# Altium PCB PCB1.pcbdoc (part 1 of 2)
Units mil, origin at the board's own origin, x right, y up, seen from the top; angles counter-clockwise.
Board outline 3543.31 x 2362.2 mil, 2 copper layers (Top Layer, Bottom Layer), stack 62.206 mil thick; 105 components, 91 nets, 439 pads, 301 vias.
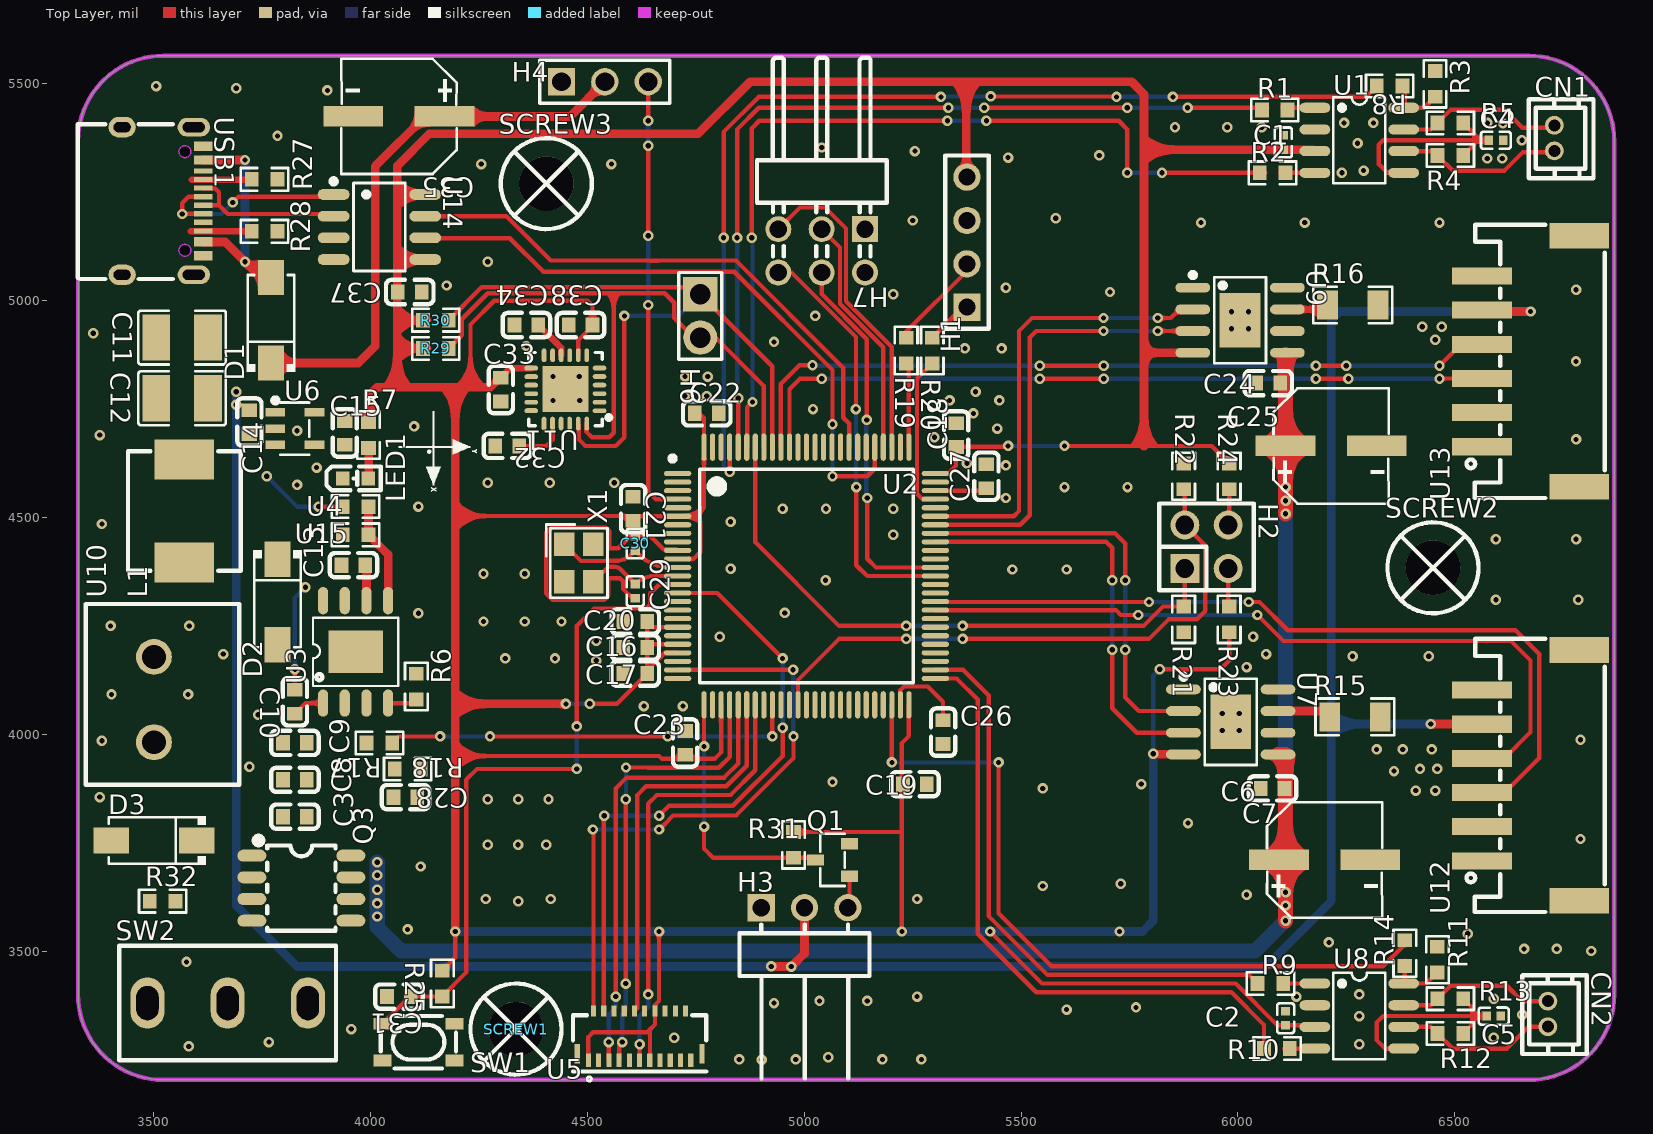
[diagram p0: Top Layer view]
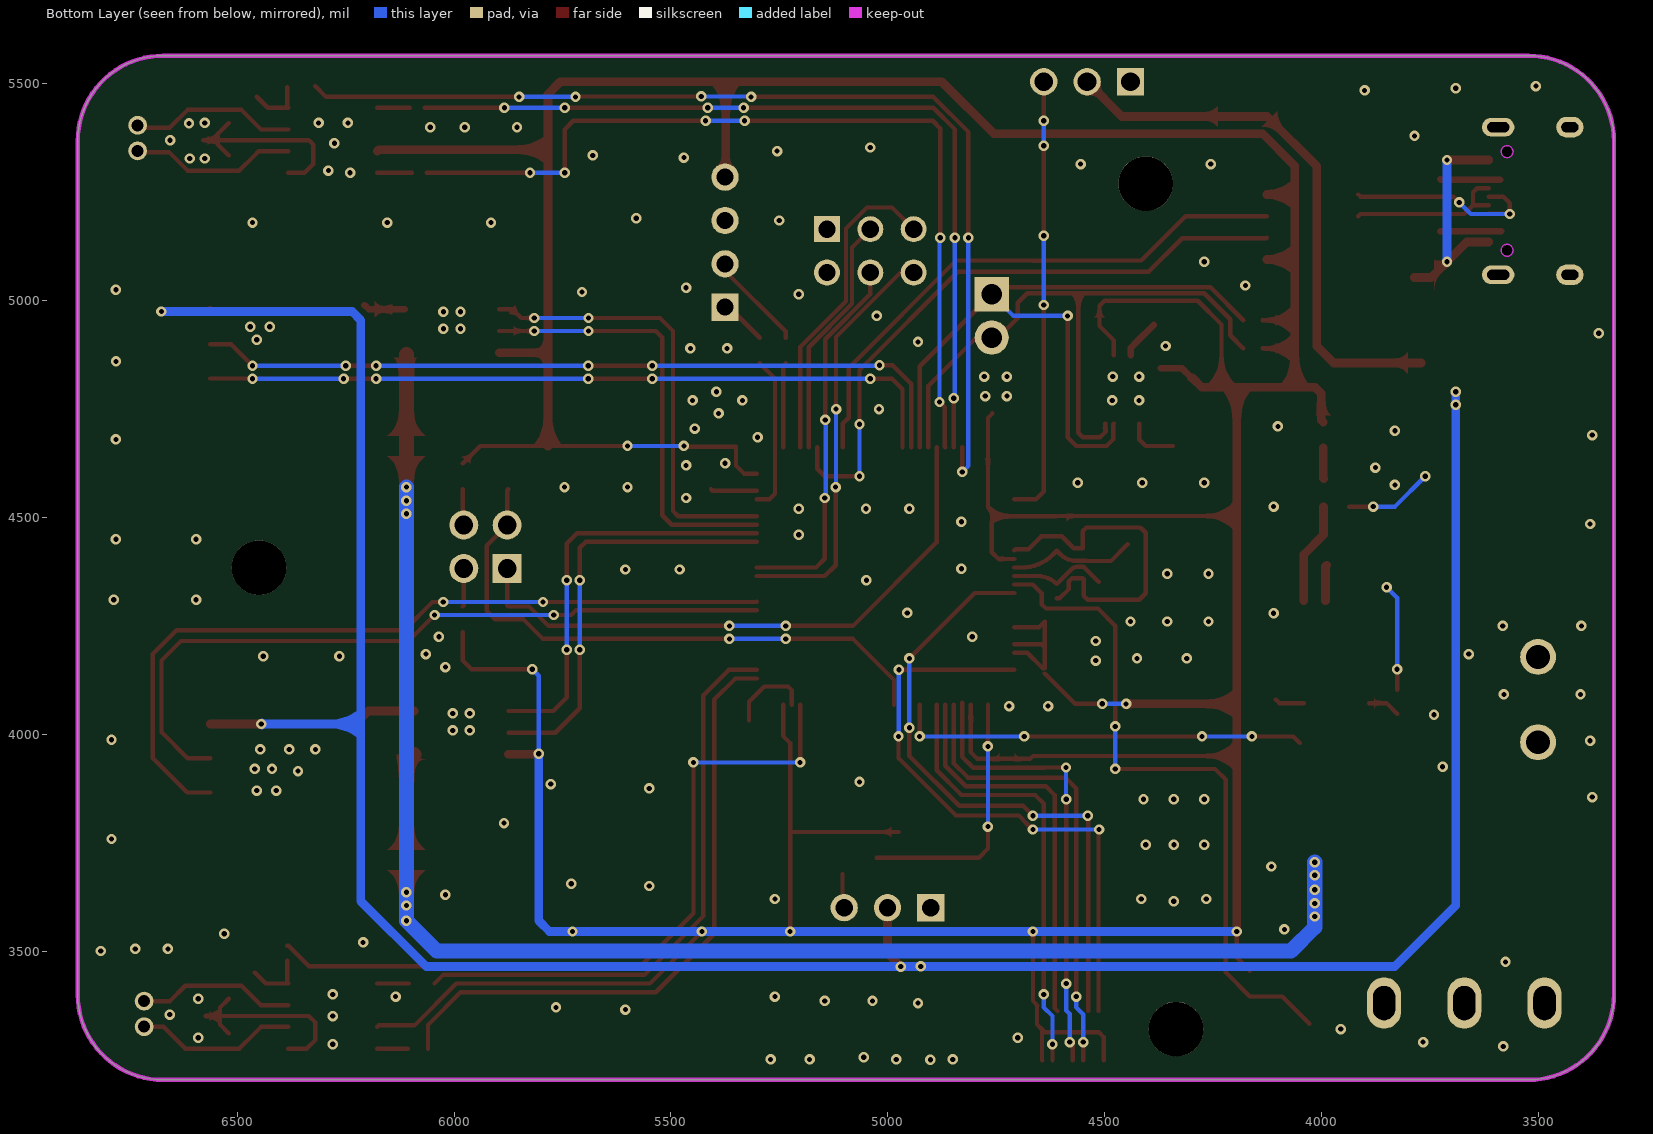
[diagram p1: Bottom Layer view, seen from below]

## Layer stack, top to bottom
Top Solder Mask Layer: solder mask 0.394, Dk 3.3
Top Layer: signal copper 1.379
Dielectric1: surface 59.449, FR4, Dk 4.5
Bottom Layer: signal copper 1.378
Bottom Solder Mask Layer: solder mask 0.394, Dk 3.3

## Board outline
3521.65,5565 ccw(c3521.65,5368.15) 3324.8,5368.15 3324.8,3399.65 ccw(c3521.65,3399.65) 3521.65,3202.8 6671.26,3202.8 ccw(c6671.26,3399.65) 6868.11,3399.65 6868.11,5368.15 ccw(c6671.26,5368.15) 6671.26,5565

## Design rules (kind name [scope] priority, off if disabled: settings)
BoardOutlineClearance copperThickness2oz_1 [All] p2 off: genericclearance=7.99 ignorepadtopadclearanceinfootprint=FALSE except(0: Arc-SplitContinuation Track-SplitContinuation SMDPad-SplitContinuation THPad-SplitContinuation Via-SplitContinuation Fill-SplitContinuation Region-SplitContinuation Poly-SplitContinuation Text-SplitContinuation Hole-SplitContinuation; 5.98: Arc-CutoutEdge SMDPad-CutoutEdge THPad-CutoutEdge Via-CutoutEdge Fill-CutoutEdge Region-CutoutEdge Text-CutoutEdge; 6.93: Hole-OutlineEdge Hole-CutoutEdge; 10: Poly-OutlineEdge Poly-CutoutEdge; 11.81: Arc-OutlineEdge Track-OutlineEdge SMDPad-OutlineEdge THPad-OutlineEdge Via-OutlineEdge Fill-OutlineEdge Region-OutlineEdge Text-OutlineEdge Track-CutoutEdge)
BoardOutlineClearance copperThickness1oz_1 [All] p4: genericclearance=4.02 ignorepadtopadclearanceinfootprint=FALSE except(0: Arc-SplitContinuation Track-SplitContinuation SMDPad-SplitContinuation THPad-SplitContinuation Via-SplitContinuation Fill-SplitContinuation Region-SplitContinuation Poly-SplitContinuation Text-SplitContinuation Hole-SplitContinuation; 6: SMDPad-CutoutEdge THPad-CutoutEdge Via-CutoutEdge Fill-CutoutEdge Region-CutoutEdge Text-CutoutEdge; 6.93: Hole-OutlineEdge Hole-CutoutEdge; 10: Poly-OutlineEdge Poly-CutoutEdge; 11.8: Arc-OutlineEdge Track-OutlineEdge SMDPad-OutlineEdge THPad-OutlineEdge Via-OutlineEdge Fill-OutlineEdge Region-OutlineEdge Text-OutlineEdge; 11.81: Arc-CutoutEdge Track-CutoutEdge)
Clearance copperThickness2oz [All] p1 off: gap=7.99 ignorepadtopadclearanceinfootprint=FALSE except(5.98: SMDPad-Track SMDPad-SMDPad THPad-Track SMDPad-THPad THPad-THPad Track-Via SMDPad-Via THPad-Via Via-Via Fill-Track Region-Track Fill-SMDPad Region-SMDPad Fill-THPad Region-THPad Fill-Via Region-Via Fill-Fill Fill-Region Region-Region Arc-Track Arc-SMDPad Arc-THPad Arc-Via Fill-Arc Region-Arc Arc-Arc Text-Track SMDPad-Text Text-THPad Text-Via Fill-Text Region-Text Arc-Text Text-Text; 6.93: Hole-Track Hole-SMDPad Hole-THPad Hole-Via Fill-Hole Region-Hole Hole-Arc Hole-Text; 10: Poly-Track Poly-SMDPad Poly-THPad Poly-Via Poly-Fill Poly-Region Poly-Poly Poly-Arc Poly-Text Poly-Hole)
Clearance copperThickness1oz [All] p3: gap=4.02 ignorepadtopadclearanceinfootprint=FALSE except(5.98: SMDPad-Track SMDPad-SMDPad THPad-Track SMDPad-THPad THPad-THPad Track-Via SMDPad-Via THPad-Via Via-Via Fill-Track Region-Track Fill-SMDPad Region-SMDPad Fill-THPad Region-THPad Fill-Via Region-Via Fill-Fill Fill-Region Region-Region; 6: Arc-Track Arc-SMDPad Arc-THPad Arc-Via Fill-Arc Region-Arc Arc-Arc Text-Track SMDPad-Text Text-THPad Text-Via Fill-Text Region-Text Arc-Text Text-Text; 6.93: Hole-Track Hole-SMDPad Hole-THPad Hole-Via Fill-Hole Region-Hole Hole-Arc Hole-Text; 10: Poly-Track Poly-SMDPad Poly-THPad Poly-Via Poly-Fill Poly-Region Poly-Poly Poly-Arc Poly-Text Poly-Hole)
Creepage creepage [All] p1: checkdistance=0 ignoreinternallayers=TRUE applytopolygonpour=TRUE
DiffPairsRouting differentialPair [All] p1: maxlimit=6 minlimit=6 mostfreqgap=6 toplayer_minwidth=5 toplayer_prefwidth=10 toplayer_maxwidth=100 toplayer_mingap=6 toplayer_prefgap=6 toplayer_maxgap=6 bottomlayer_minwidth=5 bottomlayer_prefwidth=10 bottomlayer_maxwidth=100 bottomlayer_mingap=6 bottomlayer_prefgap=6 bottomlayer_maxgap=6 maxuncoupledlength=10
HoleToHoleClearance otherClearance [All] p1: gap=11.81 allowstackedmicrovias=TRUE
Length netLength [All] p1: minlimit=0 maxlimit=0
MatchedLengths netLengthTolerance [All] p1: tolerance=1000
PasteMaskExpansion pasteMaskExpansion [All] p1: expansion=0
PlaneConnect innerPlane [All] p1: planeconnectstyle=Relief reliefexpansion=20 reliefentries=4 reliefconductorwidth=10 reliefairgap=10
PolygonConnect "copperRegion_Top Layer" [(InNet('BAT') OR InNet('3V3') OR InNet('12V') OR InNet('$1N58') OR InNet('$1N321') OR InNet('$1N322') OR InNet('BAT_ADC') OR InNet('GND') OR InNet('MOTOR1_OUT1') OR InNet('MOTOR1_OUT2') OR InNet('MOTOR2_OUT1') OR InNet('MOTOR2_OUT2')) And OnLayer('Top Layer')] p1: connectstyle=Direct reliefconductorwidth=10 reliefentries=4 polygonreliefangle="90 Angle" airgapwidth=10 via.connectstyle=Relief via.reliefconductorwidth=10 via.reliefentries=4 via.polygonreliefangle="90 Angle" via.airgapwidth=10
PolygonConnect "copperRegion_Bottom Layer" [(InNet('BAT') OR InNet('3V3') OR InNet('12V') OR InNet('$1N58') OR InNet('$1N321') OR InNet('$1N322') OR InNet('BAT_ADC') OR InNet('GND') OR InNet('MOTOR1_OUT1') OR InNet('MOTOR1_OUT2') OR InNet('MOTOR2_OUT1') OR InNet('MOTOR2_OUT2')) And OnLayer('Bottom Layer')] p2: connectstyle=Direct reliefconductorwidth=10 reliefentries=4 polygonreliefangle="90 Angle" airgapwidth=10 via.connectstyle=Relief via.reliefconductorwidth=10 via.reliefentries=4 via.polygonreliefangle="90 Angle" via.airgapwidth=10
PolygonConnect copperRegion [(InNet('BAT') OR InNet('3V3') OR InNet('12V') OR InNet('$1N58') OR InNet('$1N321') OR InNet('$1N322') OR InNet('BAT_ADC') OR InNet('GND') OR InNet('MOTOR1_OUT1') OR InNet('MOTOR1_OUT2') OR InNet('MOTOR2_OUT1') OR InNet('MOTOR2_OUT2'))] p3: connectstyle=Direct reliefconductorwidth=10 reliefentries=4 polygonreliefangle="90 Angle" airgapwidth=10 via.connectstyle=Relief via.reliefconductorwidth=10 via.reliefentries=4 via.polygonreliefangle="90 Angle" via.airgapwidth=10
RoutingVias viaSize [All] p1: holewidth=12.01 width=24.02 viastyle="Through Hole" minholewidth=11.81 minwidth=19.68 maxholewidth=248.03 maxwidth=393.7
SolderMaskExpansion solderMaskExpansion [IsVia] p1: expansion=-1000 istentingtop=TRUE
SolderMaskExpansion solderMaskExpansion [All] p2: expansion=2 istentingtop=FALSE
Width copperThickness2oz_2 [All] p1 off: maxlimit=100 minlimit=8 preferedwidth=10
Width copperThickness1oz_2 [All] p2: maxlimit=100 minlimit=5 preferedwidth=10

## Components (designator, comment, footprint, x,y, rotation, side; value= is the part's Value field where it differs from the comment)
C1 "4.7uF" C0402 6105,5365 r270 top
C2 "4.7uF" C0402 6110,3345 r270 top
C3 "2.2uF" C0603 3825,3810 r180 top
C4 "100pF" C0402 6595,5370 r0 top
C5 "100pF" C0402 6590,3350 r0 top
C6 "100nF" C0603 6080,3875 r0 top
C7 "47uF" CAP-SMD_BD6.3-L6.6-W6.6-LS7.3-FD 6200,3710 r0 top
C8 "2.2uF" C0603 3825,3895 r180 top
C9 "100nF" C0603 3825,3980 r0 top
C10 "100nF" C0603 3825,4075 r270 top
C11 "47uF" C1210 3565,4915 r0 top
C12 "47uF" C1210 3565,4775 r0 top
C13 "22nF" C0603 3960,4390 r0 top
C14 "100nF" C0603 3720,4720 r90 top
C15 "100nF" C0603 3940,4695 r90 top
C16 "100nF" C0603 4610,4200 r180 top
C17 "100nF" C0603 4610,4140 r0 top
C18 "100nF" C0603 5350,4690 r270 top
C19 "100nF" C0603 5255,3885 r180 top
C20 "100nF" C0603 4610,4260 r0 top
C21 "100nF" C0603 4605,4520 r270 top
C22 "100nF" C0603 4775,4740 r180 top
C23 "100nF" C0603 4725,3980 r270 top
C24 "100nF" C0603 6070,4810 r0 top
C25 "47uF" CAP-SMD_BD6.3-L6.6-W6.6-LS7.3-FD 6215,4665 r0 top
C26 "2.2uF" C0603 5320,4005 r270 top
C27 "2.2uF" C0603 5420,4595 r90 top
C28 "100nF" C0603 4080,3855 r180 top
C29 "12pF" C0402 4610,4330 r90 top
C30 "12pF" C0402 4610,4440 r270 top
C31 "100nF" C0603 4065,3395 r0 top
C32 "2.2nF" C0603 4315,4665 r180 top
C33 "100nF" C0603 4300,4795 r270 top
C34 "100nF" C0603 4358.93,4943.93 r0 top
C35 "100uF" CAP-SMD_BD6.3-L6.6-W6.6-LS7.3-FD-H7.7 4065,5425 r180 top
C37 "100nF" C0603 4090,5020 r180 top
C38 "10nF" C0603 4483.93,4943.93 r0 top
CN1 "ZH1.5-2A" CONN-TH_ZH-1.5-2A 6730,5375 r270 top
CN2 "ZH1.5-2A" CONN-TH_ZH-1.5-2A 6715,3355 r270 top
D1 "SS54" SMA_L4.4-W2.8-LS5.4-R-RD 3770,4955 r90 top
D2 "SS54" SMA_L4.4-W2.8-LS5.4-R-RD 3785,4305 r270 top
D3 "SS54" SMA_L4.4-W2.8-LS5.4-R-RD 3500,3755 r180 top
H1 "LAIL-PZ2.54-4P-L" CONN-TH_LAIL-PZ2.54-4P-L 5375,5135 r90 top
H2 "PZ254V-12-4P" HDR-TH_4P-P2.54-V-M-R2-C2-S2.54 5927.67,4432.33 r0 top
H3 "LAIL-PZ2.54-3P-W" HDR-TH_LAIL-PZ2.54-3P-W 5000.39,3600 r0 top locked
H4 "LAIL-PZ2.54-3P-L" HDR-TH_3P-P2.54-V-M-1 4540,5505 r0 top
H6 "PZ254V-11-02P" HDR-TH_2P-P2.54-V-M 4760,4965 r270 top
H7 "HC-PZ254-13.8L-2x3PWA" HDR-TH_6P-P2.54-H-M-R2-C3-S2.54-W12.9 5040,5115 r180 top
L1 "4.7uH" IND-SMD_L7.0-W6.6_AAPS0630 3570,4515 r90 top
LED1 "KT-0603R" LED-SMD_L1.6-W0.8-R-RD 3965,4590 r0 top
Q1 "PMBT3904" SOT-23-3_L2.9-W1.3-P1.90-LS2.4-BR 5065,3710 r0 top
Q3 "NCE4435" SOP-8_L5.0-W4.0-P1.27-LS6.2-BL 3840,3645 r270 top
R1 "100Ω" R0603 6085,5440 r0 top
R2 "100Ω" R0603 6080,5295 r0 top
R3 "10kΩ" R0603 6455,5500 r90 top
R4 "60Ω" R0603 6490,5335 r180 top
R5 "60Ω" R0603 6490,5410 r180 top
R6 "49.9kΩ" R0603 4105,4110 r270 top
R7 "10kΩ" R0603 3995,4690 r270 top
R8 "100Ω" R0603 6350,5495 r180 top
R9 "100Ω" R0603 6075,3425 r0 top
R10 "100Ω" R0603 6090,3275 r0 top
R11 "10kΩ" R0603 6460,3480 r90 top
R12 "60Ω" R0603 6490,3310 r180 top
R13 "60Ω" R0603 6490,3390 r180 top
R14 "100Ω" R0603 6385,3495 r90 top
R15 "200mΩ" R1206 6270,4040 r0 top
R16 "200mΩ" R1206 6265,4990 r0 top
R17 "30kΩ" R0603 4020,3980 r180 top
R18 "7.5kΩ" R0603 4085,3920 r180 top
R19 "100Ω" R0603 5235,4885 r270 top
R20 "100Ω" R0603 5295,4885 r270 top
R21 "10kΩ" R0603 5875,4265 r90 top
R22 "10kΩ" R0603 5875,4595 r90 top
R23 "1kΩ" R0603 5980,4265 r90 top
R24 "1kΩ" R0603 5980,4595 r90 top
R25 "10kΩ" R0603 4165,3425 r90 top
R27 "5.1kΩ" R0603 3755,5280 r180 top
R28 "5.1kΩ" R0603 3755,5160 r180 top
R29 "4.7kΩ" R0603 4150,4890 r180 top
R30 "4.7kΩ" R0603 4150,4955 r180 top
R31 "4.7kΩ" R0603 4975,3745 r90 top
R32 "10kΩ" R0603 3520,3615 r0 top
SCREW1 "" M3螺丝 4335,3320 r0 top
SCREW2 "" M3螺丝 6450,4383.9 r0 top
SCREW3 "" M3螺丝 4405,5270 r0 top
SW1 "SKRPACE010" KEY-SMD_4P-L4.2-W3.2-P2.20-LS4.6 4110,3290 r0 top
SW2 "SS-12D10L5" SW-TH_SS-12D10L5 3670,3380 r0 top
U1 "SN65HVD230DR" SOIC-8_L4.9-W3.9-P1.27-LS6.0-BL 6280,5370 r270 top
U2 "STM32F407VET6" LQFP-100_L14.0-W14.0-P0.50-LS16.0-BL 5005,4365 r270 top locked
U3 "LMR14030SDDAR" SO-8_L4.9-W3.9-P1.27-LS6.0-BL-EP 3965,4190 r0 top
U4 "91kΩ" R0603 3965,4525 r180 top
U5 "FH26W-21S-0.3SHW(60)" FPC-SMD_21P-P0.30_HDGC_0.3K-QX-21PWB 4620,3305 r0 top locked
U6 "RT9013-33GB" SOT-23-5_L3.0-W1.7-P0.95-LS2.8-BL 3825,4705 r270 top
U7 "DRV8870DDAR" HSOP-8_L5.0-W4.0-P1.27-LS6.2-BL-EP 5983.51,4028.51 r270 top
U8 "SN65HVD230DR" SOIC-8_L4.9-W3.9-P1.27-LS6.0-BL 6280,3350 r270 top
U9 "DRV8870DDAR" HSOP-8_L5.0-W4.0-P1.27-LS6.2-BL-EP 6005,4955 r270 top
U10 "DG305-5.0-02P-12-00A(H)" CONN-TH_2P-P2.50_DG305-5.0-02P-12-00A-H 3500,4080 r270 top
U11 "MPU-6050" QFN-24_L4.0-W4.0-P0.50-BL-EP2.7 4448.93,4795.38 r90 top
U12 "WAFER-PH2.0-6PWB" CONN-SMD_6P-P2.00_XUNPU_WAFER-PH2.0-6PWB 6675,3905 r90 top
U13 "WAFER-PH2.0-6PWB" CONN-SMD_6P-P2.00_XUNPU_WAFER-PH2.0-6PWB 6675,4860 r90 top
U14 "CH340N" SOP-8_L4.9-W3.9-P1.27-LS6.0-BL 4020,5170 r270 top
U15 "12kΩ" R0603 3965,4460 r0 top
USB1 "TYPE-C 16PIN 2MD(073)" USB-C-SMD_TYPE-C-16PIN-2MD-073 3520,5230 r270 top
X1 "8MHz" CRYSTAL-SMD_4P-L3.2-W2.5-BL 4480,4395 r270 top

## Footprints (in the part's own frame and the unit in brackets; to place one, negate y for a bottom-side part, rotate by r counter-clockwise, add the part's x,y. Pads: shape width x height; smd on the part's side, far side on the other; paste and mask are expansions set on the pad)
C0402 [mm]
  rect 0.5x0.54 smd: 1(-0.42,0) 2(0.42,0)
  silkscreen extent -0.87,-0.5 0.87,0.5
C0603 [mm]
  rect 0.8x0.9 smd: 1(-0.7,0) 2(0.7,0)
  silkscreen extent -1.39,-0.71 1.39,0.71
C1210 [mm]
  rect 1.635x2.7 smd paste-100 mask+0.051: 1(-1.517,0) 2(1.517,0)
  silkscreen extent -2.56,-1.58 2.56,1.58
CAP-SMD_BD6.3-L6.6-W6.6-LS7.3-FD [mm]
  rect 3.5x1.2 smd: 1(-2.67,0) 2(2.67,0)
  silkscreen extent -3.38,-3.38 3.38,3.38
CAP-SMD_BD6.3-L6.6-W6.6-LS7.3-FD-H7.7 [mm]
  rect 3.5x1.2 smd: 1(-2.67,0) 2(2.67,0)
  silkscreen extent -3.38,-3.38 3.38,3.38
CONN-SMD_6P-P2.00_XUNPU_WAFER-PH2.0-6PWB [mm]
  rect 1x3.5 smd paste+0 mask+0.05: 1(-5,2.85) 2(-3,2.85) 3(-1,2.85) 4(1,2.85) 5(3,2.85) 6(5,2.85)
  rect 1.5x3.5 smd paste+0 mask+0.05: 7(-7.35,-2.85) 8(7.35,-2.85)
  silkscreen extent -8,-4.35 8,3.75
CONN-TH_2P-P2.50_DG305-5.0-02P-12-00A-H [mm]
  round 2.1 hole 1.4: 1(-2.5,0) 2(2.5,0)
  silkscreen extent -5.6,-4 5,5
CONN-TH_LAIL-PZ2.54-4P-L [mm]
  rect 1.6x1.6 hole 1 paste+0 mask+0.051: 1(-3.81,0)
  round 1.6 hole 1 paste+0 mask+0.051: 2(-1.27,0) 3(1.27,0) 4(3.81,0)
  silkscreen extent -5.08,-1.27 5.08,1.27
CONN-TH_ZH-1.5-2A [mm]
  round 1.1 hole 0.7: 1(-0.751,0) 2(0.751,0)
  silkscreen extent -2.27,-1.5 2.35,2.29
CRYSTAL-SMD_4P-L3.2-W2.5-BL [mm]
  rect 1.4x1.2 smd: 1(-1.1,-0.85) 2(1.1,-0.85) 3(1.1,0.85) 4(-1.1,0.85)
  silkscreen extent -2.26,-1.91 2.03,1.68
FPC-SMD_21P-P0.30_HDGC_0.3K-QX-21PWB [mm]
  rect 0.3x0.8 smd paste+0 mask+0.05: 1(-3,-1.438) 3(-2.4,-1.438) 5(-1.8,-1.438) 7(-1.2,-1.438) 9(-0.6,-1.438) 11(0,-1.438) 13(0.6,-1.438) 15(1.2,-1.438) 17(1.8,-1.438) 19(2.4,-1.438) 21(3,-1.438)
  rect 0.3x0.65 smd paste+0 mask+0.05: 2(-2.7,1.438) 4(-2.1,1.438) 6(-1.5,1.438) 8(-0.9,1.438) 10(-0.3,1.438) 12(0.3,1.438) 14(0.9,1.438) 16(1.5,1.438) 18(2.1,1.438) 20(2.7,1.438)
  rect 0.3x1.15 smd paste+0 mask+0.05: 22(3.65,-1.062) 23(-3.65,-1.062)
  silkscreen extent -3.9,-2.67 3.9,1.2
HDR-TH_2P-P2.54-V-M [mm]
  rect 2x2 hole 1.2: 1(-1.27,0)
  round 2 hole 1.2: 2(1.27,0)
  silkscreen extent -2.54,-1.27 2.54,1.27
HDR-TH_3P-P2.54-V-M-1 [mm]
  rect 1.575x1.6 hole 1.1 paste+0 mask+0.05: 1(-2.54,0)
  round 1.6 hole 1.1 paste+0 mask+0.05: 2(0,0) 3(2.54,0)
  silkscreen extent -3.81,-1.27 3.81,1.27
HDR-TH_4P-P2.54-V-M-R2-C2-S2.54 [mm]
  rect 1.7x1.7 hole 1.1: 1(-1.27,-1.27)
  round 1.7 hole 1.1: 2(-1.27,1.27) 3(1.27,-1.27) 4(1.27,1.27)
  silkscreen extent -2.77,-2.54 2.77,2.54
HDR-TH_6P-P2.54-H-M-R2-C3-S2.54-W12.9 [mm]
  rect 1.52x1.52 hole 1.02 paste+0 mask+0.05: 1(-2.54,-1.27)
  round 1.52 hole 1.02 paste+0 mask+0.05: 2(-2.54,1.27) 3(0,-1.27) 4(0,1.27) 5(2.54,-1.27) 6(2.54,1.27)
  silkscreen extent -3.81,-11.31 3.79,0.33
HDR-TH_LAIL-PZ2.54-3P-W [mm]
  rect 1.6x1.6 hole 1.02 paste+0 mask+0.05: 1(-2.54,0)
  round 1.6 hole 1.02 paste+0 mask+0.05: 2(0,0) 3(2.54,0)
  silkscreen extent -3.81,-10 3.81,-0.98
HSOP-8_L5.0-W4.0-P1.27-LS6.2-BL-EP [mm]
  oval 0.574x2.038 smd: 1(-1.905,-2.769) 2(-0.635,-2.769) 3(0.635,-2.769) 4(1.905,-2.769) 5(1.905,2.769) 6(0.635,2.769) 7(-0.635,2.769) 8(-1.905,2.769)
  rect 3.2x2.4 smd: 9(0,0)
  silkscreen extent -2.79,-2.92 2.53,1.52
IND-SMD_L7.0-W6.6_AAPS0630 [mm]
  rect 2.35x3.5 smd: 1(-3.025,0) 2(3.025,0)
  silkscreen extent -3.5,-3.3 3.5,3.3
KEY-SMD_4P-L4.2-W3.2-P2.20-LS4.6 [mm]
  rect 1.05x0.7 smd: 1(-2.1,1.075) 2(2.1,1.075) 3(-2.1,-1.075) 4(2.1,-1.075)
  silkscreen extent -2.2,-1.55 2.2,1.52
LED-SMD_L1.6-W0.8-R-RD [mm]
  rect 0.8x0.8 smd paste+0 mask+0.051: 1(0.75,0) 2(-0.75,0)
  silkscreen extent -1.7,-0.7 1.47,0.7
LQFP-100_L14.0-W14.0-P0.50-LS16.0-BL [mm]
  oval 0.3x1.6 smd: 1(-6,-7.55) 2(-5.5,-7.55) 3(-5,-7.55) 4(-4.5,-7.55) 5(-4,-7.55) 6(-3.5,-7.55) 7(-3,-7.55) 8(-2.5,-7.55) 9(-2,-7.55) 10(-1.5,-7.55) 11(-1,-7.55) 12(-0.5,-7.55) 13(0,-7.55) 14(0.5,-7.55) 15(1,-7.55) 16(1.5,-7.55) 17(2,-7.55) 18(2.5,-7.55) 19(3,-7.55) 20(3.5,-7.55) 21(4,-7.55) 22(4.5,-7.55) 23(5,-7.55) 24(5.5,-7.55) 25(6,-7.55) 51(6,7.55) 52(5.5,7.55) 53(5,7.55) 54(4.5,7.55) 55(4,7.55) 56(3.5,7.55) 57(3,7.55) 58(2.5,7.55) 59(2,7.55) 60(1.5,7.55) 61(1,7.55) 62(0.5,7.55) 63(0,7.55) 64(-0.5,7.55) 65(-1,7.55) 66(-1.5,7.55) 67(-2,7.55) 68(-2.5,7.55) 69(-3,7.55) 70(-3.5,7.55) 71(-4,7.55) 72(-4.5,7.55) 73(-5,7.55) 74(-5.5,7.55) 75(-6,7.55)
  oval 1.6x0.3 smd: 26(7.55,-6) 27(7.55,-5.5) 28(7.55,-5) 29(7.55,-4.5) 30(7.55,-4) 31(7.55,-3.5) 32(7.55,-3) 33(7.55,-2.5) 34(7.55,-2) 35(7.55,-1.5) 36(7.55,-1) 37(7.55,-0.5) 38(7.55,0) 39(7.55,0.5) 40(7.55,1) 41(7.55,1.5) 42(7.55,2) 43(7.55,2.5) 44(7.55,3) 45(7.55,3.5) 46(7.55,4) 47(7.55,4.5) 48(7.55,5) 49(7.55,5.5) 50(7.55,6) 76(-7.55,6) 77(-7.55,5.5) 78(-7.55,5) 79(-7.55,4.5) 80(-7.55,4) 81(-7.55,3.5) 82(-7.55,3) 83(-7.55,2.5) 84(-7.55,2) 85(-7.55,1.5) 86(-7.55,1) 87(-7.55,0.5) 88(-7.55,0) 89(-7.55,-0.5) 90(-7.55,-1) 91(-7.55,-1.5) 92(-7.55,-2) 93(-7.55,-2.5) 94(-7.55,-3) 95(-7.55,-3.5) 96(-7.55,-4) 97(-7.55,-4.5) 98(-7.55,-5) 99(-7.55,-5.5) 100(-7.55,-6)
  silkscreen extent -7.03,-8 6.25,6.25
M3螺丝 [mil]
  round 126 hole 126 paste+0 mask+4: 1(0,0)
  silkscreen extent -105,-105 105,105
QFN-24_L4.0-W4.0-P0.50-BL-EP2.7 [mm]
  oval 0.28x0.8 smd paste-100 mask+0.05: 1(-1.25,-2) 2(-0.75,-2) 3(-0.25,-2) 4(0.25,-2) 5(0.75,-2) 6(1.25,-2) 13(1.25,2) 14(0.75,2) 15(0.25,2) 16(-0.25,2) 17(-0.75,2) 18(-1.242,2)
  oval 0.8x0.28 smd paste-100 mask+0.05: 7(2,-1.25) 8(2,-0.75) 9(2,-0.25) 10(2,0.25) 11(2,0.75) 12(2,1.25) 19(-2,1.25) 20(-2,0.75) 21(-2,0.25) 22(-2,-0.25) 23(-2,-0.75) 24(-2,-1.25)
  rect 2.7x2.7 smd paste-100 mask+0.05: 25(0.012,0)
  silkscreen extent -2.14,-2.79 2.16,2.15
R0603 [mil]
  rect 31.75x34.02 smd paste-3937.01 mask+2: 1(-29.66,0) 2(29.66,0)
  silkscreen extent -55,-26 55,26
R1206 [mil]
  rect 47.54x66.97 smd paste-3937.01 mask+2: 1(-58.22,0) 2(58.22,0)
  silkscreen extent -91,-42 91,42
SMA_L4.4-W2.8-LS5.4-R-RD [mil]
  rect 81.2x60.59 smd: 1(98.57,0) 2(-98.57,0)
  silkscreen extent -119,-56 104,56
SO-8_L4.9-W3.9-P1.27-LS6.0-BL-EP [mm]
  oval 0.6x1.6 smd: 1(-1.905,-3) 2(-0.635,-3) 3(0.635,-3) 4(1.905,-3) 5(1.905,3) 6(0.635,3) 7(-0.635,3) 8(-1.905,3)
  rect 3.2x2.5 smd: 9(0,0)
  silkscreen extent -2.5,-2 2.5,2
SOIC-8_L4.9-W3.9-P1.27-LS6.0-BL [mm]
  oval 0.588x1.8 smd paste+0 mask+0.051: 1(-1.905,-2.6) 2(-0.635,-2.6) 3(0.635,-2.6) 4(1.905,-2.6) 5(1.905,2.6) 6(0.635,2.6) 7(-0.635,2.6) 8(-1.905,2.6)
  silkscreen extent -2.53,-1.52 2.53,1.52
SOP-8_L4.9-W3.9-P1.27-LS6.0-BL [mm]
  oval 0.63x1.865 smd: 1(-1.905,-2.682) 2(-0.635,-2.682) 3(0.635,-2.682) 4(1.905,-2.682) 5(1.905,2.682) 6(0.635,2.682) 7(-0.635,2.682) 8(-1.905,2.682)
  silkscreen extent -2.82,-2.83 2.58,1.52
SOP-8_L5.0-W4.0-P1.27-LS6.2-BL [mm]
  oval 0.7x1.7 smd: 1(-1.905,-2.9) 2(-0.635,-2.9) 3(0.635,-2.9) 4(1.905,-2.9) 5(1.905,2.9) 6(0.635,2.9) 7(-0.635,2.9) 8(-1.905,2.9)
  silkscreen extent -2.99,-2.71 2.5,2
SOT-23-3_L2.9-W1.3-P1.90-LS2.4-BR [mm]
  rect 1x0.65 smd: 1(1,-0.95) 2(1,0.95) 3(-1,0)
  silkscreen extent -0.73,-1.53 0.73,1.53
SOT-23-5_L3.0-W1.7-P0.95-LS2.8-BL [mm]
  rect 0.49x1.157 smd: 1(-0.95,-1.154) 2(0,-1.154) 3(0.95,-1.154)
  rect 0.49x1.175 smd: 4(0.95,1.154) 5(-0.95,1.154)
  silkscreen extent -1.8,-1.29 1.53,0.85
SW-TH_SS-12D10L5 [mm]
  oval 2x3 hole 1.3 slot 2 at 90 deg: 1(-4.7,0) 2(0,0) 3(4.7,0)
  silkscreen extent -6.35,-3.35 6.35,3.35
USB-C-SMD_TYPE-C-16PIN-2MD-073 [mm]
  oval 1.1x1.9 hole 0.6 slot 1.3 at 90 deg paste+0 mask+0.05: 13(-4.325,1.825) 14(4.325,1.825)
  oval 1.2x1.6 hole 0.6 slot 1 at 90 deg paste+0 mask+0.05: 13(-4.325,-2.375) 14(4.325,-2.375)
  rect 0.55x1.1 smd paste+0 mask+0.05: A1B12(-3.2,2.375) A4B9(-2.4,2.375) B1A12(3.2,2.375) B4A9(2.4,2.375)
  rect 0.3x1.1 smd paste+0 mask+0.05: A5(-1.25,2.375) A6(-0.25,2.375) A7(0.25,2.375) A8(1.25,2.375) B5(1.75,2.375) B6(0.75,2.375) B7(-0.75,2.375) B8(-1.75,2.375)
  Board Outline Layer circle w0.003: c-2.89,1.305 r0.35
  Board Outline Layer circle w0.003: c2.89,1.305 r0.35
  Board Outline Layer region: -2.89,1.655 -2.738,1.62 -2.616,1.523 -2.549,1.383 -2.549,1.227 -2.616,1.087 -2.738,0.99 -2.89,0.955 -2.89,0.955 -3.042,0.99 -3.164,1.087 -3.231,1.227 -3.231,1.383 -3.164,1.523 -3.042,1.62 -2.89,1.655
  Board Outline Layer region: -2.89,1.655 -2.812,1.646 -2.738,1.62 -2.672,1.579 -2.616,1.523 -2.575,1.457 -2.549,1.383 -2.54,1.305 -2.549,1.227 -2.575,1.153 -2.616,1.087 -2.672,1.031 -2.738,0.99 -2.812,0.964 -2.89,0.955 -2.968,0.964 -3.042,0.99 -3.108,1.031 -3.164,1.087 -3.205,1.153 -3.231,1.227 -3.24,1.305 -3.231,1.383 -3.205,1.457 -3.164,1.523 -3.108,1.579 -3.042,1.62 -2.968,1.646
  Board Outline Layer region: 2.89,1.655 3.042,1.62 3.164,1.523 3.231,1.383 3.231,1.227 3.164,1.087 3.042,0.99 2.89,0.955 2.89,0.955 2.738,0.99 2.616,1.087 2.549,1.227 2.549,1.383 2.616,1.523 2.738,1.62 2.89,1.655
  Board Outline Layer region: 2.89,1.655 2.968,1.646 3.042,1.62 3.108,1.579 3.164,1.523 3.205,1.457 3.231,1.383 3.24,1.305 3.231,1.227 3.205,1.153 3.164,1.087 3.108,1.031 3.042,0.99 2.968,0.964 2.89,0.955 2.812,0.964 2.738,0.99 2.672,1.031 2.616,1.087 2.575,1.153 2.549,1.227 2.54,1.305 2.549,1.383 2.575,1.457 2.616,1.523 2.672,1.579 2.738,1.62 2.812,1.646
  Multi-Layer board cut-out: -2.89,1.655 -2.738,1.62 -2.616,1.523 -2.549,1.383 -2.549,1.227 -2.616,1.087 -2.738,0.99 -2.89,0.955 -2.89,0.955 -3.042,0.99 -3.164,1.087 -3.231,1.227 -3.231,1.383 -3.164,1.523 -3.042,1.62 -2.89,1.655
  Multi-Layer board cut-out: 2.89,1.655 3.042,1.62 3.164,1.523 3.231,1.383 3.231,1.227 3.164,1.087 3.042,0.99 2.89,0.955 2.89,0.955 2.738,0.99 2.616,1.087 2.549,1.227 2.549,1.383 2.616,1.523 2.738,1.62 2.89,1.655
  silkscreen extent -4.5,-4.97 4.57,0.6

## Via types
v1: diameter 24.02, hole 12, Top Layer to Bottom Layer, 293 vias
v2: diameter 24, hole 12, Top Layer to Bottom Layer, 8 vias

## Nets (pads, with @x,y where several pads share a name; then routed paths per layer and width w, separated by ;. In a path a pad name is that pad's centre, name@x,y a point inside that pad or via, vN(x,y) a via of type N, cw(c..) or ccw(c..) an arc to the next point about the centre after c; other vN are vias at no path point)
3V3: C1.2 C2.2 C15.2 C16.1 C17.2 C18.2 C19.2 C20.2 C21.2 C22.2 C23.2 C33.1 C37.2 C38.2 H1.4 R7.1 R23.1 R24.2 R25.2 R29.2 R30.2 R31.2 U1.3 U2.6 U2.11 U2.19 U2.21 U2.22 U2.28 U2.50 U2.75 U2.100 U5.1 U5.13 U5.14 U6.5 U7.4 U8.3 U9.4 U11.8 U11.13 U14.5 U14.8 | length 14421
  Top Layer w10: 4060.86,4890 R29.2@4135.34,4890 ; 4060.86,4955 R30.2@4135.34,4955 ; R25.2@4165,3454.66 4165,3455 4195,3485 v1(4195,3545) ; 4195,3950 4665,3950 4671.86,3943.14 4793.14,3943.14 4808.15,3958.15 U2.28@4808.15,4067.76 ; 4195,4503.46 C21.2@4605,4503.46 ; 4230,4800 4230,4945 4285,5000 4500,5000 4511.49,4988.51 C38.2@4511.49,4943.93 4511.49,4941.49 4478.24,4908.24 4478.24,4874.34 U11.8@4478.46,4874.12 ; U5.1@4501.89,3248.41 4501.89,3301.89 4512.99,3312.99 4637.99,3312.99 4643.62,3318.62 ; v1(4505,4070.26) 4567.82,4070.26 C17.2@4637.56,4140 ; C21.2@4610.66,4502.8 U2.6@4707.76,4502.8 4747.2,4502.8 ; U5.13@4643.62,3248.41 4643.95,3248.73 4643.95,3318.29 4643.62,3318.62 ; v1(4665,3545) 4665,3385 4655.43,3375.43 U5.14@4655.43,3361.59 4655.43,3330.43 4643.62,3318.62 ; U2.22@4707.76,4187.83 4677.96,4187.83 4642.69,4152.56 4637.56,4152.56 C16.1@4637.56,4200 ; U2.21@4707.76,4207.52 4645.08,4207.52 C16.1@4637.56,4200 ; U2.19@4707.76,4246.89 4650.67,4246.89 C20.2@4637.56,4260 C16.1@4637.56,4200 ; U2.11@4707.76,4404.37 4744.37,4404.37 4760,4420 4760,4490 4747.2,4502.8 ; C22.2@4758.46,4740 4768.78,4729.68 4768.78,4721.75 U2.100@4768.78,4662.24 4768.78,4524.38 4747.2,4502.8 ; R31.2@4975,3774.66 5225,3774.66 ; v1(5225,3545) 5225,3774.66 ; U2.50@5241.22,4067.76 5241.22,3996.22 5225,3980 5225,3774.66 ; U2.75@5302.24,4601.22 5331.22,4601.22 5350,4620 5350,4663.46 5468.46,4663.46 v1(5470,4665) ; v1(5428.47,3545) 5548.47,3425 5995,3425 6091.54,3328.46 C2.2@6110,3328.46 6174.18,3328.46 U8.3@6177.63,3325 ; v1(5600,4665) 5783.59,4665 5939.66,4665 R24.2@5980,4624.66 ; v1(5820,4150) 5960,4150 5980,4170 R23.1@5980,4235.34
  Top Layer w15: C33.1@4300,4822.56 4322.03,4844.59 U11.13@4370.19,4844.59
  Top Layer w20: R7.1@3995,4719.66 4000,4724.66 4000,4785.86 4014.14,4800 4060.86,4800 ; U14.5@4125.61,5095 4060.86,5095 ; U14.8@4125.61,5245 4060.86,5245 ; v1(4195,3545) 4195,3950 4195,4070 ; C33.1@4300,4822.56 4297.56,4822.56 4275,4800 4230,4800 4195,4800 ; v1(4450,4070) 4195,4070 ; H1.4@5375,5285 5373.34,5286.65 5373.34,5505 ; 5783.59,4665 5783.59,4880 ; v1(5805,3955) 5806.49,3953.51 U7.4@5874.49,3953.51 ; U9.4@5895.98,4880 5812.06,4880 5783.59,4880 ; U1.3@6177.63,5345 6174.18,5348.46 C1.2@6105,5348.46 5786.54,5348.46 5783.59,5351.41 ; 4060.86,4800 4060.86,4890 4060.86,4955 4060.86,5095 ; 4060.86,4800 4195,4800 ; 4060.86,5095 4060.86,5245 ; 4060.86,5245 4060.86,5310.86 4135.39,5385.39 4755.39,5385.39 4875,5505 5373.34,5505 ; 4195,4070 4195,4503.46 4195,4800 ; 5373.34,5505 5755,5505 5783.59,5476.41 5783.59,5351.41 ; 5783.59,4880 5783.59,5351.41
  Bottom Layer w10: v1(4450,4070) 4504.74,4070 v1(4505,4070.26) ; v1(5470,4665) v1(5600,4665) ; v1(5805,3955) 5805,4135 v1(5820,4150)
  Bottom Layer w20: v1(4195,3545) v1(4665,3545) v1(5225,3545) v1(5428.47,3545) v1(5726.86,3545) 5780,3545 5805,3570 v1(5805,3955)
5V: C11.2 C12.2 C14.2 C35.1 D1.2 H3.2 H4.2 L1.2 U4.2 U6.1 U6.3 U12.5 U13.5 | length 7781.3
  Top Layer w10: v1(3880,4525) U4.2@3935.34,4525
  Top Layer w20: D1.2@3770,4856.43 3971.43,4856.43 4010,4895 4010,5310 4125,5425 4215.12,5425 4460,5425 H4.2@4540,5505 ; v1(4923.87,3464.51) 4969.51,3464.51 v1(4970,3464.02) 5000.39,3494.41 H3.2@5000.39,3600 ; v1(6445,4023.6) 6562.3,4023.6 U12.5@6562.8,4023.11 ; U13.5@6562.8,4978.11 6565.9,4975 v1(6675,4975)
  Bottom Layer w10: v1(3760,4595) 3830,4525 v1(3880,4525)
  Bottom Layer w20: v1(3690,4790) v1(3690,4760) 3690,3605 3830.49,3464.51 v1(4923.87,3464.51) 6064.51,3464.51 6215,3615 6215,4023.6 ; v1(6445,4023.6) 6215,4023.6 ; v1(6675,4975) 6235,4975 6215,4955 6215,4023.6
12V: C3.1 C6.2 C7.1 C8.1 C9.2 C24.2 C25.1 Q3.5 Q3.6 Q3.7 Q3.8 R17.2 U3.2 U3.3 U7.5 U9.5 | length 4065.3
  Top Layer w35: U7.5@6092.53,3953.51 6110,3953.51 v1(6110,3635.4) v1(6110,3605) v1(6110,3570) ; v1(6110,4508.41) v1(6110,4538.5) v1(6110,4570) U9.5@6110,4875.98
  Bottom Layer w35: v1(4015,3705) v1(4015,3675) v1(4015,3641.49) v1(4015,3609.92) v1(4015,3579.59) 4015,3555 4070,3500 6040,3500 v1(6110,3570) v1(6110,3605) v1(6110,3635.4) v1(6110,4508.41) v1(6110,4538.5) v1(6110,4570)
$1N8: R2.2 U1.4 | length 80.6
  Top Layer w10: R2.2@6097.04,5295 U1.4@6177.63,5295
$1N10: R3.1 R8.1 U1.8 | length 132.2
  Top Layer w10: R8.1@6385,5492.96 6385,5447.64 U1.8@6382.37,5445 6429.66,5445 R3.1@6455,5470.34
$1N19: C4.1 R4.1 R5.1 U1.5 | length 465.4
  Top Layer w10: U1.5@6382.37,5295 6345,5295 6325,5315 6325,5360 6335,5370 6543.58,5370 6545,5371.42 ; R4.1@6519.66,5335 6545,5360.34 6545,5371.42 ; R5.1@6519.66,5410 6545,5384.66 6545,5371.42 ; C4.1@6578.46,5370 6546.42,5370 6545,5371.42
$1N29: R1.2 U1.1 | length 75.6
  Top Layer w10: R1.2@6102.04,5445 U1.1@6177.63,5445
$1N58: C10.1 D2.2 L1.1 U3.8 | length 246.7
  Top Layer w10: C10.1@3825,4102.56 v1(3825,4150)
  Bottom Layer w10: v1(3825,4150) 3825,4315 v1(3849.21,4339.21)
$1N59: C10.2 U3.1 | length 75.1
  Top Layer w10: C10.2@3825,4047.44 3849.45,4071.89 U3.1@3890,4071.89
$1N65: C13.2 U3.6 | length 82.9
  Top Layer w20: C13.2@3987.56,4390 3990,4387.56 U3.6@3990,4308.11
$1N66: R6.2 U3.4 | length 68.5
  Top Layer w10: U3.4@4040,4071.89 4096.55,4071.89 R6.2@4105,4080.34
$1N74: LED1.1 R7.2 | length 70.5
  Top Layer w20: LED1.1@3994.53,4590 3995,4590.47 R7.2@3995,4660.34
$1N85: R9.2 U8.1 | length 73
  Top Layer w10: R9.2@6104.66,3425 U8.1@6177.63,3425
$1N87: C5.1 R12.1 R13.1 U8.5 | length 467.2
  Top Layer w10: U8.5@6382.37,3275 6340,3275 6320,3295 6320,3335 6335.09,3350.09 6540,3350.09 ; R12.1@6519.66,3310 6540,3330.34 6540,3350.09 ; R13.1@6519.66,3390 6540,3369.66 6540,3350.09 ; C5.1@6573.46,3350 6540.09,3350 6540,3350.09
$1N91: R11.1 R14.1 U8.8 | length 142.2
  Top Layer w10: R14.1@6385,3477.96 6385,3427.64 U8.8@6382.37,3425 6434.66,3425 R11.1@6460,3450.34
$1N93: R10.2 U8.4 | length 70.6
  Top Layer w10: R10.2@6107.04,3275 U8.4@6177.63,3275
$1N101: R15.1 U7.7 | length 124.8
  Top Layer w20: U7.7@6092.53,4053.51 6198.27,4053.51 R15.1@6211.78,4040
$1N112: R16.1 U9.7 | length 96.9
  Top Layer w15: U9.7@6114.02,4980 6196.78,4980 R16.1@6206.78,4990
$1N117: C26.1 U2.49 | length 193
  Top Layer w10: U2.49@5221.54,4067.76 5221.54,4101.78 5230,4110.24 5284.76,4110.24 5320,4075 C26.1@5320,4032.56
$1N118: C27.1 U2.73 | length 106.5
  Top Layer w10: U2.73@5302.24,4561.85 5404.29,4561.85 C27.1@5407.44,4565
$1N154: H1.2 R19.1 | length 228.3
  Top Layer w10: R19.1@5235,4914.66 5235,4928.8 5375,5068.8 H1.2@5375,5085
$1N155: H1.1 R20.1 | length 109.1
  Top Layer w10: R20.1@5295,4914.66 5365.34,4985 H1.1@5375,4985
$1N173: H2.4 R24.1 | length 84
  Top Layer w10: H2.4@5977.67,4482.33 5980,4484.66 R24.1@5980,4565.34
$1N174: H2.3 R23.2 | length 88.6
  Top Layer w10: H2.3@5977.67,4382.33 5977.67,4296.99 R23.2@5980,4294.66
$1N188: R28.2 USB1.B5 | length 140.3
  Top Layer w15: 3585,5160 R28.2@3725.34,5160
$1N189: R27.2 USB1.A5 | length 138.9
  Top Layer w15: 3586.86,5278.91 3724.25,5278.91 R27.2@3725.34,5280
$1N208: C32.1 U11.20 | length 120
  Top Layer w10: C32.1@4342.56,4665 4405,4665 4419.4,4679.4 U11.20@4419.4,4716.64
$1N211: C34.2 U11.10 | length 91.7
  Top Layer w15: C34.2@4386.49,4943.93 4427.06,4903.35 4427.26,4903.35 4438.39,4892.23 4438.39,4892.02 4439.09,4891.33 U11.10@4439.09,4874.12
$1N241: U2.7
$1N242: U2.8
$1N279: D1.1 USB1.A4B9 USB1.B4A9 | length 536.4
  Top Layer w20: USB1.B4A9@3613.51,5135.51 3664.49,5135.51 v1(3710,5090) 3746.43,5053.57 D1.1@3785,5053.57 ; USB1.A4B9@3613.51,5324.48 v1(3710,5324.48)
  Bottom Layer w20: v1(3710,5090) v1(3710,5324.48)
$1N321: Q3.4 SW2.2
$1N322: D3.1 R32.1 SW2.1
BAT: D3.2 Q3.1 Q3.2 Q3.3 SW2.3 U10.2
BAT_ADC: C28.2 R17.1 R18.2 U2.34 | length 955.6
  Top Layer w10: R17.1@4049.66,3980 4064.66,3995 v1(4160,3995) ; v1(4275,3995) v1(4685,3995) ; v1(4926.26,3995) U2.34@4926.26,4067.76
  Bottom Layer w10: v1(4160,3995) v1(4275,3995) ; v1(4685,3995) v1(4926.26,3995)
BOOT0: H2.1 R21.2 U2.94 | length 1394.5
  Top Layer w10: U2.94@4886.89,4662.24 4886.89,4443.11 5080,4250 v1(5235,4250) ; v1(5365,4250) 5782.52,4250 5827.18,4294.66 R21.2@5875,4294.66 5877.67,4297.33 H2.1@5877.67,4382.33
  Bottom Layer w10: v1(5235,4250) v1(5365,4250)
BOOT1: H2.2 R22.1 U2.37 | length 1364.4
  Top Layer w10: U2.37@4985.32,4067.76 4985.32,4125.32 5080,4220 v1(5235,4220) ; v1(5365,4220) 5795,4220 5840,4265 5905,4265 5925,4285 5925,4435 H2.2@5877.67,4482.33 5877.67,4562.67 R22.1@5875,4565.34
  Bottom Layer w10: v1(5235,4220) v1(5365,4220)
CAN1_H: CN1.1 R5.2 U1.7 | length 385.4
  Top Layer w10: U1.7@6382.37,5395 6445.34,5395 R5.2@6460.34,5410 6490.34,5440 6615,5440 6655.78,5399.22 6724.67,5399.22 CN1.1@6730,5404.55
CAN1_L: CN1.2 R4.2 U1.6 | length 385.1
  Top Layer w10: U1.6@6382.37,5345 6450.34,5345 R4.2@6460.34,5335 6495.34,5300 6615,5300 6657.73,5342.73 6727.28,5342.73 CN1.2@6730,5345.45
CAN1_RS: R8.2 U2.97 | length 2398.3
  Top Layer w10: v1(4813.85,5145) 4813.85,5388.85 4895,5470 v1(5315,5470) ; v1(4827.83,4605) U2.97@4827.83,4662.24 ; v1(5429.78,5471.11) 5718.89,5471.11 v1(5720,5470) ; v1(5850,5470) 6295.34,5470 R8.2@6320.34,5495
  Bottom Layer w10: v1(4813.85,5145) 4813.85,4618.98 v1(4827.83,4605) ; v1(5315,5470) 5316.11,5471.11 v1(5429.78,5471.11) ; v1(5720,5470) v1(5850,5470)
CAN1_RX: R2.1 U2.95 | length 2041.4
  Top Layer w10: U2.95@4867.2,4662.24 4868.6,4663.64 4868.6,4754.49 v1(4880.51,4766.4) ; v1(4878.6,5145) 4878.6,5397.44 4896.16,5415 v1(5330,5415) ; v1(5420,5415) 5725,5415 5745,5395 v1(5745,5295) ; v1(5825,5295) R2.1@6062.96,5295
  Bottom Layer w10: v1(4878.6,5145) 4880.51,5143.09 v1(4880.51,4766.4) ; v1(5330,5415) v1(5420,5415) ; v1(5745,5295) v1(5825,5295)
CAN1_TX: R1.1 U2.96 | length 1977.4
  Top Layer w10: v1(4845,5145) 4845,5395 4895,5445 v1(5332.43,5445) ; U2.96@4847.52,4662.24 v1(4847.52,4775) ; v1(5415,5445) v1(5745,5445) ; v1(5883.92,5445.02) R1.1@6067.94,5445.02
  Bottom Layer w10: v1(4845,5145) 4845,4777.52 v1(4847.52,4775) ; v1(5332.43,5445) v1(5415,5445) ; v1(5745,5445) v1(5883.92,5445.02)
CAN2_H: CN2.1 R13.2 U8.7 | length 366
  Top Layer w10: U8.7@6382.37,3375 6445.34,3375 R13.2@6460.34,3390 6490.34,3420 6620,3420 6655.45,3384.55 CN2.1@6715,3384.55
CAN2_L: CN2.2 R12.2 U8.6 | length 374.2
  Top Layer w10: U8.6@6382.37,3325 6445.34,3325 R12.2@6460.34,3310 6495.34,3275 6620,3275 6670.45,3325.45 CN2.2@6715,3325.45
CAN2_RS: R14.2 U2.48 | length 1732.7
  Top Layer w10: U2.48@5201.85,4067.76 5201.85,3937.01 v1@5203.86,3935 ; v1(5447.99,3935) 5447.99,3587.01 5570,3465 6334.74,3465 6381.78,3512.04 R14.2@6385,3512.04
  Bottom Layer w10: v1@5203.86,3935 v1(5447.99,3935)
  other v1: 5202.01,3935
CAN2_RX: R10.1 U2.51 | length 1460.1
  Top Layer w10: U2.51@5302.24,4128.78 5351.22,4128.78 5400,4080 5400,3540 5535,3405 5985,3405 6060.34,3329.66 R10.1@6060.34,3275
CAN2_TX: R9.1 U2.52 | length 1340.8
  Top Layer w10: U2.52@5302.24,4148.46 5366.36,4148.46 5425,4089.82 5425,3580.99 5560.99,3445 6025.34,3445 R9.1@6045.34,3425
D2: U5.9
D3: U5.8
D+: U14.1 USB1.A6 USB1.B6 | length 496.4
  Top Layer w10: USB1.B6@3613.51,5200.47 3565.47,5200.48 v1(3565,5200) 3565,5225 3579.84,5239.85 USB1.A6@3613.51,5239.84 ; v1(3681.56,5226.56) 3695,5240 3909.39,5240 U14.1@3914.39,5245
  Bottom Layer w10: v1(3565,5200) 3655,5200 v1(3681.56,5226.56)
D-: U14.2 USB1.A7 USB1.B7 | length 381.7
  Top Layer w10: USB1.A7@3613.51,5220.15 3613.66,5220 3650,5220 ; USB1.B7@3613.51,5259.52 3640.47,5259.52 3650,5250 3650,5220 ; U14.2@3914.39,5195 3909.39,5200 3670,5200 3650,5220
FB: U3.5 U4.1 U15.2 | length 235.7
  Top Layer w20: U4.1@3994.66,4525 U15.2@3994.66,4460 4040,4414.66 U3.5@4040,4308.11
